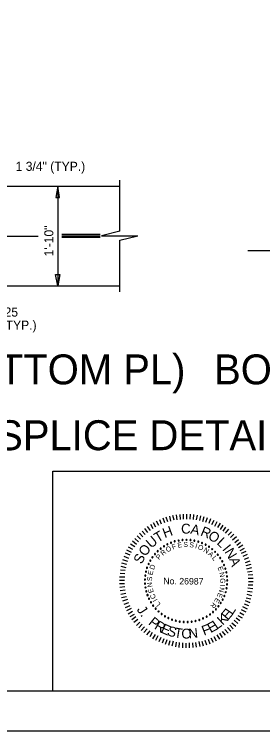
# Model space of a CAD drawing. Extents: x 1970675.2 to 1970715, y 796143 to 796167.2.
# Drawn here: x 1970699.6 to 1970703.03, y 796143.05 to 796152.92 of the extents above; entities that cross this region are included whole.
import ezdxf

# ---------------------------------------------------------------- set-up
doc = ezdxf.new("R2010")
doc.units = 0
for name, color, linetype in [('BR_AUTO DIMENSION', 7, 'Continuous'), ('BR_BORDER LINES', 7, 'Continuous'), ('BR_CENTER LINES', 7, 'Continuous'), ('BR_STRUCTURAL STEEL', 7, 'Continuous'), ('BR_TEXT', 7, 'Continuous'), ('Default', 7, 'Continuous'), ('Level 31', 7, 'Continuous')]:
    doc.layers.add(name, color=color, linetype=linetype)

msp = doc.modelspace()

# ---------------------------------------------------------------- linework, layer by layer
at = {"layer": 'BR_AUTO DIMENSION'}
msp.add_line((1970700.2036, 796150.5506), (1970700.2036, 796149.1756), dxfattribs=at)
for points in [[(1970700.1775, 796150.3943), (1970700.2296, 796150.3943), (1970700.2036, 796150.5506)], [(1970700.2336, 796149.3316), (1970700.2036, 796149.1756), (1970700.1736, 796149.3316)]]:
    msp.add_lwpolyline(points, close=True, dxfattribs=at)
at = {"layer": 'BR_BORDER LINES'}
for p, q in [((1970700.1337, 796146.6214), (1970706.0354, 796146.6214)), ((1970700.1337, 796143.5963), (1970700.1337, 796146.6214)), ((1970677.2531, 796143.5963), (1970714.2857, 796143.5963))]:
    msp.add_line(p, q, dxfattribs=at)
at = {"layer": 'BR_CENTER LINES'}
for p, q in [((1970695.5874, 796149.8631), (1970699.9325, 796149.8631)), ((1970700.7897, 796149.8631), (1970700.2578, 796149.8631)), ((1970702.8268, 796149.6662), (1970703.471, 796149.6662))]:
    msp.add_line(p, q, dxfattribs=at)
at = {"layer": 'BR_STRUCTURAL STEEL'}
for p, q in [((1970697.1441, 796150.5506), (1970701.0582, 796150.5506)), ((1970700.7897, 796149.8826), (1970700.2578, 796149.8826)), ((1970700.7897, 796149.8435), (1970700.2578, 796149.8435)), ((1970697.1441, 796149.1756), (1970701.0582, 796149.1756))]:
    msp.add_line(p, q, dxfattribs=at)
at = {"layer": 'BR_TEXT'}
for p, q in [((1970701.8516, 796145.9538), (1970701.8417, 796146.0208)), ((1970701.895, 796145.9581), (1970701.8909, 796146.0252)), ((1970701.9385, 796145.9606), (1970701.9391, 796146.0314)), ((1970701.9847, 796145.963), (1970701.9853, 796146.031)), ((1970702.031, 796145.9599), (1970702.0335, 796146.0306)), ((1970702.0753, 796145.9566), (1970702.0806, 796146.0236)), ((1970702.1178, 796145.9516), (1970702.1297, 796146.0185)), ((1970701.596, 796145.8728), (1970701.5673, 796145.9344)), ((1970701.6368, 796145.8913), (1970701.6108, 796145.9529)), ((1970701.6794, 796145.9099), (1970701.6564, 796145.9743)), ((1970701.7229, 796145.9237), (1970701.6989, 796145.9871)), ((1970701.7627, 796145.9347), (1970701.7481, 796146.0018)), ((1970701.8081, 796145.9456), (1970701.7926, 796146.0109)), ((1970702.1621, 796145.9427), (1970702.1777, 796146.0077)), ((1970702.2073, 796145.931), (1970702.2248, 796145.9979)), ((1970702.2478, 796145.9194), (1970702.2719, 796145.9824)), ((1970702.2911, 796145.9048), (1970702.3152, 796145.9688)), ((1970702.3306, 796145.8856), (1970702.3613, 796145.9467)), ((1970702.3701, 796145.8664), (1970702.4045, 796145.9275)), ((1970701.448, 796145.7759), (1970701.404, 796145.831)), ((1970701.485, 796145.8039), (1970701.442, 796145.8599)), ((1970701.5192, 796145.8272), (1970701.4857, 796145.8869)), ((1970701.5581, 796145.8533), (1970701.5246, 796145.913)), ((1970702.4114, 796145.8462), (1970702.4468, 796145.9054)), ((1970702.448, 796145.8195), (1970702.4853, 796145.8787)), ((1970702.4846, 796145.7956), (1970702.5248, 796145.851)), ((1970702.5203, 796145.767), (1970702.5651, 796145.8214)), ((1970701.3472, 796145.6851), (1970701.2994, 796145.7318)), ((1970701.3795, 796145.7188), (1970701.3308, 796145.7674)), ((1970701.4118, 796145.7488), (1970701.366, 796145.7982)), ((1970702.555, 796145.7393), (1970702.6026, 796145.788)), ((1970702.5859, 796145.7089), (1970702.6335, 796145.7566)), ((1970702.6168, 796145.6746), (1970702.669, 796145.7205)), ((1970701.2909, 796145.6138), (1970701.2365, 796145.6577)), ((1970701.3195, 796145.6504), (1970701.2651, 796145.6933)), ((1970702.6467, 796145.6394), (1970702.698, 796145.6815)), ((1970702.6728, 796145.6024), (1970702.727, 796145.6454)), ((1970701.221, 796145.504), (1970701.159, 796145.5347)), ((1970701.2402, 796145.5416), (1970701.1811, 796145.577)), ((1970701.267, 796145.5819), (1970701.2078, 796145.6183)), ((1970702.697, 796145.5701), (1970702.7549, 796145.6055)), ((1970702.7213, 796145.5293), (1970702.7801, 796145.5638)), ((1970701.1826, 796145.4212), (1970701.1186, 796145.4453)), ((1970701.2018, 796145.4635), (1970701.1388, 796145.4914)), ((1970702.7408, 796145.4914), (1970702.8043, 796145.5211)), ((1970702.7603, 796145.4506), (1970702.8228, 796145.4775)), ((1970702.7788, 796145.408), (1970702.8413, 796145.4311)), ((1970701.1555, 796145.3374), (1970701.0886, 796145.354)), ((1970701.169, 796145.377), (1970701.1013, 796145.402)), ((1970702.7935, 796145.3635), (1970702.857, 796145.3875)), ((1970702.8046, 796145.3238), (1970702.8707, 796145.3393)), ((1970701.1359, 796145.2517), (1970701.0689, 796145.2607)), ((1970701.1475, 796145.2912), (1970701.0788, 796145.3088)), ((1970702.8136, 796145.2774), (1970702.8798, 796145.2939)), ((1970702.8227, 796145.2377), (1970702.8879, 796145.2457)), ((1970701.1276, 796145.163), (1970701.0568, 796145.1636)), ((1970701.1308, 796145.2064), (1970701.0629, 796145.2145)), ((1970702.8299, 796145.1924), (1970702.897, 796145.1993)), ((1970702.8314, 796145.1489), (1970702.8975, 796145.1484)), ((1970701.1268, 796145.0705), (1970701.056, 796145.0692)), ((1970701.1253, 796145.1177), (1970701.0564, 796145.1183)), ((1970701.1293, 796145.028), (1970701.0613, 796145.0201)), ((1970702.8306, 796145.0564), (1970702.8967, 796145.054)), ((1970702.8339, 796145.1036), (1970702.9009, 796145.1031)), ((1970701.1337, 796144.9827), (1970701.0665, 796144.9728)), ((1970701.1446, 796144.9391), (1970701.0756, 796144.9246)), ((1970702.8205, 796144.9687), (1970702.8855, 796144.9578)), ((1970702.8284, 796145.014), (1970702.8954, 796145.0049)), ((1970701.1518, 796144.8928), (1970701.0846, 796144.8773)), ((1970701.1647, 796144.8521), (1970701.0965, 796144.8291)), ((1970702.7892, 796144.8387), (1970702.8523, 796144.8146)), ((1970702.8009, 796144.8792), (1970702.8668, 796144.8626)), ((1970702.8107, 796144.9254), (1970702.8767, 796144.9097)), ((1970701.1775, 796144.8095), (1970701.1132, 796144.7865)), ((1970701.1961, 796144.7688), (1970701.1326, 796144.7391)), ((1970702.7545, 796144.7559), (1970702.8166, 796144.7252)), ((1970702.7737, 796144.7964), (1970702.8359, 796144.7722)), ((1970701.2146, 796144.729), (1970701.1521, 796144.6965)), ((1970701.2332, 796144.6882), (1970701.1734, 796144.6538)), ((1970701.2593, 796144.6474), (1970701.1995, 796144.613)), ((1970702.6893, 796144.6356), (1970702.7466, 796144.6002)), ((1970702.7142, 796144.676), (1970702.7725, 796144.6406)), ((1970702.7344, 796144.7164), (1970702.7974, 796144.6829)), ((1970701.2826, 796144.6151), (1970701.2275, 796144.575)), ((1970701.3106, 796144.5781), (1970701.2555, 796144.5351)), ((1970701.3377, 796144.5411), (1970701.2892, 796144.4961)), ((1970702.6378, 796144.5671), (1970702.6884, 796144.5233)), ((1970702.6646, 796144.6037), (1970702.718, 796144.5627)), ((1970701.3695, 796144.5125), (1970701.3201, 796144.4628)), ((1970701.4014, 796144.4792), (1970701.3547, 796144.4286)), ((1970701.437, 796144.4506), (1970701.3922, 796144.399)), ((1970702.5093, 796144.4417), (1970702.5532, 796144.3894)), ((1970702.5445, 796144.4697), (1970702.5912, 796144.4184)), ((1970702.5759, 796144.5025), (1970702.6227, 796144.4521)), ((1970702.6073, 796144.5306), (1970702.6588, 796144.4848)), ((1970701.4736, 796144.4219), (1970701.4297, 796144.3694)), ((1970701.5074, 796144.398), (1970701.4729, 796144.3408)), ((1970701.5459, 796144.3732), (1970701.5114, 796144.314)), ((1970701.5835, 796144.3512), (1970701.5537, 796144.2901)), ((1970702.3575, 796144.3448), (1970702.391, 796144.2831)), ((1970702.3992, 796144.3662), (1970702.4336, 796144.3064)), ((1970702.4362, 796144.3904), (1970702.4726, 796144.3325)), ((1970702.4732, 796144.4137), (1970702.5124, 796144.3605)), ((1970701.6239, 796144.332), (1970701.597, 796144.2708)), ((1970701.6662, 796144.3127), (1970701.6421, 796144.2506)), ((1970701.7095, 796144.2992), (1970701.6844, 796144.2352)), ((1970701.7491, 796144.2856), (1970701.7334, 796144.2206)), ((1970701.7943, 796144.2777), (1970701.7777, 796144.2098)), ((1970701.8376, 796144.265), (1970701.8267, 796144.201)), ((1970701.881, 796144.26), (1970701.8757, 796144.192)), ((1970701.9244, 796144.2568), (1970701.9239, 796144.1888)), ((1970701.9706, 796144.2536), (1970701.9701, 796144.1865)), ((1970702.0169, 796144.256), (1970702.0183, 796144.188)), ((1970702.0613, 796144.2585), (1970702.0654, 796144.1905)), ((1970702.1038, 796144.2628), (1970702.1146, 796144.1986)), ((1970702.1483, 796144.2748), (1970702.1628, 796144.2067)), ((1970702.1936, 796144.2819), (1970702.2101, 796144.2167)), ((1970702.2343, 796144.2948), (1970702.2574, 796144.2304)), ((1970702.2779, 796144.3077), (1970702.301, 796144.2452)), ((1970702.3177, 796144.3262), (1970702.3474, 796144.2646))]:
    msp.add_line(p, q, dxfattribs=at)
for centre, start, end in [((1970701.7158, 796145.6148), 27.21914, 207.21914), ((1970701.7657, 796145.6374), 21.68068, 201.68068), ((1970701.7657, 796145.6374), 201.68068, 21.68068), ((1970701.8176, 796145.6551), 16.14222, 196.14222), ((1970701.8176, 796145.6551), 196.14222, 16.14222), ((1970701.8709, 796145.6677), 10.60376, 190.60376), ((1970701.8709, 796145.6677), 190.60376, 10.60376), ((1970701.9253, 796145.675), 5.06529, 185.06529), ((1970701.9253, 796145.675), 185.06529, 5.06529), ((1970701.98, 796145.6771), 359.52683, 179.52683), ((1970701.98, 796145.6771), 179.52683, 359.52683), ((1970702.0347, 796145.6739), 173.98837, 353.98837), ((1970702.0347, 796145.6739), 353.98837, 173.98837), ((1970702.0889, 796145.6654), 168.44991, 348.44991), ((1970702.0889, 796145.6654), 348.44991, 168.44991), ((1970702.142, 796145.6518), 162.91145, 342.91145), ((1970702.142, 796145.6518), 342.91145, 162.91145), ((1970702.1935, 796145.633), 157.37299, 337.37299), ((1970702.1935, 796145.633), 337.37299, 157.37299), ((1970701.5822, 796145.5199), 43.83453, 223.83453), ((1970701.5822, 796145.5199), 223.83453, 43.83453), ((1970701.6236, 796145.5558), 38.29606, 218.29606), ((1970701.6236, 796145.5558), 218.29606, 38.29606), ((1970701.6682, 796145.5875), 32.7576, 212.7576), ((1970701.6682, 796145.5875), 212.7576, 32.7576), ((1970701.7158, 796145.6148), 207.21914, 27.21914), ((1970702.243, 796145.6094), 151.83453, 331.83453), ((1970702.243, 796145.6094), 331.83453, 151.83453), ((1970702.2899, 796145.5812), 146.29606, 326.29606), ((1970702.2899, 796145.5812), 326.29606, 146.29606), ((1970702.3339, 796145.5485), 140.7576, 320.7576), ((1970702.3339, 796145.5485), 320.7576, 140.7576), ((1970701.5107, 796145.4369), 54.91145, 234.91145), ((1970701.5107, 796145.4369), 234.91145, 54.91145), ((1970701.5444, 796145.4801), 49.37299, 229.37299), ((1970701.5444, 796145.4801), 229.37299, 49.37299), ((1970702.3746, 796145.5117), 135.21914, 315.21914), ((1970702.3746, 796145.5117), 315.21914, 135.21914), ((1970702.4115, 796145.4712), 129.68068, 309.68068), ((1970702.4115, 796145.4712), 309.68068, 129.68068), ((1970702.4444, 796145.4273), 124.14222, 304.14222), ((1970702.4444, 796145.4273), 304.14222, 124.14222), ((1970701.4565, 796145.3417), 65.98837, 245.98837), ((1970701.4565, 796145.3417), 245.98837, 65.98837), ((1970701.4813, 796145.3906), 60.44991, 240.44991), ((1970701.4813, 796145.3906), 240.44991, 60.44991), ((1970702.4728, 796145.3805), 118.60376, 298.60376), ((1970702.4728, 796145.3805), 298.60376, 118.60376), ((1970702.4966, 796145.3311), 113.06529, 293.06529), ((1970702.4966, 796145.3311), 293.06529, 113.06529), ((1970701.4216, 796145.2379), 77.06529, 257.06529), ((1970701.4216, 796145.2379), 257.06529, 77.06529), ((1970701.4365, 796145.2907), 71.52683, 251.52683), ((1970701.4365, 796145.2907), 251.52683, 71.52683), ((1970702.5155, 796145.2796), 107.52683, 287.52683), ((1970702.5155, 796145.2796), 287.52683, 107.52683), ((1970702.5294, 796145.2266), 101.98837, 281.98837), ((1970702.5294, 796145.2266), 281.98837, 101.98837), ((1970701.4073, 796145.1294), 88.14222, 268.14222), ((1970701.4118, 796145.184), 82.60376, 262.60376), ((1970701.4073, 796145.1294), 268.14222, 88.14222), ((1970701.4118, 796145.184), 262.60376, 82.60376), ((1970702.538, 796145.1725), 96.44991, 276.44991), ((1970702.538, 796145.1725), 276.44991, 96.44991), ((1970701.408, 796145.0746), 93.68068, 273.68068), ((1970701.408, 796145.0746), 273.68068, 93.68068), ((1970701.4141, 796145.0201), 279.21914, 99.21914), ((1970702.5396, 796145.063), 85.37299, 265.37299), ((1970702.5414, 796145.1178), 90.91145, 270.91145), ((1970702.5396, 796145.063), 265.37299, 85.37299), ((1970702.5414, 796145.1178), 270.91145, 90.91145), ((1970701.4141, 796145.0201), 99.21914, 279.21914), ((1970701.4254, 796144.9665), 104.7576, 284.7576), ((1970701.4254, 796144.9665), 284.7576, 104.7576), ((1970702.52, 796144.9552), 74.29606, 254.29606), ((1970702.52, 796144.9552), 254.29606, 74.29606), ((1970702.5324, 796145.0086), 79.83453, 259.83453), ((1970702.5324, 796145.0086), 259.83453, 79.83453), ((1970701.4418, 796144.9142), 110.29606, 290.29606), ((1970701.4418, 796144.9142), 290.29606, 110.29606), ((1970701.4632, 796144.8637), 115.83453, 295.83453), ((1970701.4632, 796144.8637), 295.83453, 115.83453), ((1970702.4801, 796144.8533), 63.21914, 243.21914), ((1970702.4801, 796144.8533), 243.21914, 63.21914), ((1970702.5025, 796144.9033), 68.7576, 248.7576), ((1970702.5025, 796144.9033), 248.7576, 68.7576), ((1970701.4893, 796144.8155), 121.37299, 301.37299), ((1970701.4893, 796144.8155), 301.37299, 121.37299), ((1970701.52, 796144.7701), 126.91145, 306.91145), ((1970701.52, 796144.7701), 306.91145, 126.91145), ((1970701.5549, 796144.7278), 132.44991, 312.44991), ((1970701.5549, 796144.7278), 312.44991, 132.44991), ((1970702.4214, 796144.7608), 52.14222, 232.14222), ((1970702.4214, 796144.7608), 232.14222, 52.14222), ((1970702.453, 796144.8056), 57.68068, 237.68068), ((1970702.453, 796144.8056), 237.68068, 57.68068), ((1970701.5937, 796144.6891), 137.98837, 317.98837), ((1970701.5937, 796144.6891), 317.98837, 137.98837), ((1970701.6361, 796144.6544), 143.52683, 323.52683), ((1970701.6361, 796144.6544), 323.52683, 143.52683), ((1970702.3029, 796144.6476), 35.52683, 215.52683), ((1970702.3029, 796144.6476), 215.52683, 35.52683), ((1970702.346, 796144.6814), 41.06529, 221.06529), ((1970702.346, 796144.6814), 221.06529, 41.06529), ((1970702.3856, 796144.7193), 46.60376, 226.60376), ((1970702.3856, 796144.7193), 226.60376, 46.60376), ((1970701.6816, 796144.6239), 149.06529, 329.06529), ((1970701.6816, 796144.6239), 329.06529, 149.06529), ((1970701.7299, 796144.5979), 154.60376, 334.60376), ((1970701.7299, 796144.5979), 334.60376, 154.60376), ((1970701.7805, 796144.5767), 160.14222, 340.14222), ((1970701.7805, 796144.5767), 340.14222, 160.14222), ((1970701.8328, 796144.5605), 165.68068, 345.68068), ((1970701.8328, 796144.5605), 345.68068, 165.68068), ((1970701.8865, 796144.5494), 171.21914, 351.21914), ((1970701.8865, 796144.5494), 351.21914, 171.21914), ((1970701.941, 796144.5436), 356.7576, 176.7576), ((1970701.941, 796144.5436), 176.7576, 356.7576), ((1970701.9958, 796144.543), 2.29606, 182.29606), ((1970701.9958, 796144.543), 182.29606, 2.29606), ((1970702.0504, 796144.5477), 7.83453, 187.83453), ((1970702.0504, 796144.5477), 187.83453, 7.83453), ((1970702.1043, 796144.5577), 13.37299, 193.37299), ((1970702.1043, 796144.5577), 193.37299, 13.37299), ((1970702.157, 796144.5729), 18.91145, 198.91145), ((1970702.157, 796144.5729), 198.91145, 18.91145), ((1970702.208, 796144.593), 24.44991, 204.44991), ((1970702.208, 796144.593), 204.44991, 24.44991), ((1970702.2568, 796144.618), 29.98837, 209.98837), ((1970702.2568, 796144.618), 209.98837, 29.98837)]:
    msp.add_arc(centre, 0.00771, start, end, dxfattribs=at)
at = {"layer": 'Default'}
for p, q in [((1970701.0582, 796149.9288), (1970701.0582, 796150.6339)), ((1970701.0582, 796149.9288), (1970700.8064, 796149.8684)), ((1970700.8064, 796149.8684), (1970701.31, 796149.8684)), ((1970701.0582, 796149.8079), (1970701.31, 796149.8684)), ((1970701.0582, 796149.0922), (1970701.0582, 796149.8079))]:
    msp.add_line(p, q, dxfattribs=at)
at = {"layer": 'Level 31'}
msp.add_lwpolyline([(1970675.2365, 796167.2463), (1970675.2365, 796143.0464), (1970714.8364, 796143.0464), (1970714.8364, 796167.2463)], dxfattribs=at)

# ---------------------------------------------------------------- texts
at = {"layer": 'BR_TEXT'}
for s, height, p in [('1 3/4" (TYP.)', 0.125, (1970699.6222, 796150.7617)), ('7/8" DIA. A325', 0.125, (1970698.5558, 796148.7528)), ('HS BOLTS (TYP.)', 0.125, (1970698.5558, 796148.5727)), ('BOTTOM FLANGE (BOTTOM PL)', 0.4125, (1970693.5378, 796147.8194)), ('BOTTOM FILLER PLATE', 0.4125, (1970702.3607, 796147.8194)), ('FIELD SPLICE DETAIL (TYPE 2)', 0.4125, (1970697.6374, 796146.912))]:
    msp.add_text(s, height=height, dxfattribs=at).set_placement(p)
for s, height, rotation, p in [('1\'-10"', 0.125, 90, (1970700.143, 796149.5828)), ('H', 0.1365, 20.36371, (1970701.6798, 796145.6983)), ('C', 0.1365, 359.54822, (1970701.9047, 796145.7625)), ('A', 0.1365, 348.19813, (1970702.0273, 796145.7633)), ('R', 0.1365, 337.43439, (1970702.1628, 796145.7415)), ('U', 0.1365, 40.80225, (1970701.4939, 796145.5528)), ('T', 0.1365, 30.49921, (1970701.5832, 796145.635)), ('O', 0.1363, 326.58689, (1970702.2643, 796145.701)), ('F', 0.0685, 20.61271, (1970701.7912, 796145.5411)), ('E', 0.0685, 11.41035, (1970701.8629, 796145.565)), ('S', 0.0685, 2.20798, (1970701.9375, 796145.5771)), ('S', 0.0685, 352.66081, (1970702.0159, 796145.5769)), ('I', 0.0685, 343.11363, (1970702.0932, 796145.5636)), ('L', 0.1365, 315.94879, (1970702.3881, 796145.6265)), ('O', 0.1365, 52.0267, (1970701.4119, 796145.4385)), ('R', 0.0685, 40.39491, (1970701.6554, 796145.4533)), ('O', 0.0685, 30.84774, (1970701.7171, 796145.5015)), ('O', 0.0685, 338.43918, (1970702.13, 796145.5525)), ('N', 0.0685, 328.20415, (1970702.2065, 796145.518)), ('I', 0.1365, 308.66128, (1970702.4666, 796145.5448)), ('N', 0.1365, 300.70365, (1970702.5003, 796145.5125)), ('S', 0.1363, 63.25114, (1970701.362, 796145.3333)), ('P', 0.0685, 49.94209, (1970701.6025, 796145.3954)), ('A', 0.0685, 318.65698, (1970702.2714, 796145.4739)), ('L', 0.0685, 309.45461, (1970702.3262, 796145.4219)), ('D', 0.0685, 69.03644, (1970701.5288, 796145.2576)), ('A', 0.1365, 289.47921, (1970702.5654, 796145.4101)), ('E', 0.0685, 78.23881, (1970701.5106, 796145.1843)), ('E', 0.0685, 291.049, (1970702.4074, 796145.295)), ('N', 0.0685, 281.84664, (1970702.4318, 796145.2235)), ('S', 0.0685, 87.78598, (1970701.5043, 796145.1061)), ('No. 26987', 0.08992, 359.52683, (1970701.6595, 796145.0638)), ('G', 0.0685, 272.29946, (1970702.4447, 796145.1462)), ('N', 0.0685, 97.33316, (1970701.5111, 796145.028)), ('I', 0.0685, 262.40836, (1970702.4444, 796145.065)), ('E', 0.0685, 106.53552, (1970701.5298, 796144.9548)), ('C', 0.0685, 116.42662, (1970701.5627, 796144.8806)), ('E', 0.0685, 248.18673, (1970702.4195, 796144.951)), ('N', 0.0685, 257.73391, (1970702.4394, 796145.0269)), ('I', 0.0685, 121.10107, (1970701.5826, 796144.8477)), ('E', 0.0685, 238.98437, (1970702.3888, 796144.882)), ('J', 0.1359, 302.95589, (1970701.2886, 796144.715)), ('L', 0.0685, 129.95951, (1970701.6273, 796144.7903)), ('R', 0.0685, 229.78201, (1970702.3474, 796144.8188)), ('L', 0.1359, 56.42474, (1970702.6124, 796144.6334)), ('.', 0.1359, 309.39736, (1970701.3371, 796144.6402)), ('K', 0.1359, 42.30307, (1970702.4773, 796144.4928)), ('E', 0.1359, 49.3639, (1970702.5492, 796144.5589)), ('P', 0.1359, 321.10348, (1970701.4454, 796144.5201)), ('R', 0.1359, 328.53593, (1970701.526, 796144.4562)), ('E', 0.1359, 28.1814, (1970702.312, 796144.3894)), ('L', 0.1359, 35.24223, (1970702.3978, 796144.436)), ('E', 0.1359, 335.96839, (1970701.6141, 796144.4033)), ('S', 0.1359, 343.02922, (1970701.7035, 796144.364)), ('T', 0.1359, 350.46168, (1970701.8021, 796144.3349)), ('O', 0.1359, 358.14189, (1970701.9071, 796144.3184)), ('N', 0.1359, 5.82209, (1970702.0133, 796144.3161)), ('F', 0.1359, 21.12057, (1970702.2211, 796144.3537))]:
    msp.add_text(s, height=height, rotation=rotation, dxfattribs=at).set_placement(p)

doc.saveas('drawing.dxf')
